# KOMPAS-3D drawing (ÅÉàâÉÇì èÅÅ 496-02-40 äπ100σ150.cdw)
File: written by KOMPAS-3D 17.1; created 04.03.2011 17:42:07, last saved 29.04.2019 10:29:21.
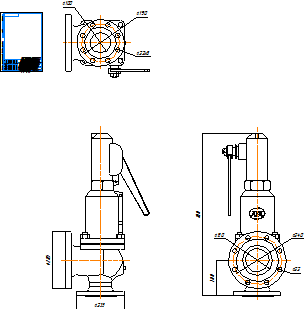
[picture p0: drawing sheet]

Sheet 1: A4, portrait

Title block, sheet 1: name: ПРЕГРАН КПП 496-02-40 / Ду100х150; material: Внимание! Данный продукт является объектом авторского права ООО «Торговый Дом АДЛ». / Запрещается изменение, копирование, распространение / (в том числе путем копирования на другие сайты и ресурсы в Интернете) / или любое иное использование информации и объектов без предварительного / согласия правообладателя (ООО «Торговый Дом АДЛ»).; scale: 1:1; sheets: 1; organisation: ООО "Торговый дом АДЛ"; sheet format: A4; stored path: C:\Users\tra\Desktop\2д чертежи\Предохранительные клапаны ПРЕГРАН\ПРЕГРАН 496\ПРЕГРАН КПП 496-02-40\KOMPAS 2D\ПРЕГРАН КПП 496-02-40 Ду100х150.cdw

Views: Спереди 1, Проекционный вид 2, Проекционный вид 3
Dimensions and other numbers on the sheet: 235; 285; 180; 810; 240; 22; 150; 190; 100; 1:1; 1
